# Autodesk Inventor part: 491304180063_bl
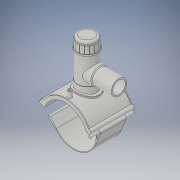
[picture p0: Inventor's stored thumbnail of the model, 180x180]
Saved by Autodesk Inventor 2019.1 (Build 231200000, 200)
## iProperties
Created: 2017-07
Part Number: 491304180063_bl
Material: Generic
Description: PLASSON TAPPING TEE SADDLE 180mm x 63mm
Document SubType Name: Modeling
Designer: KIM
Mass: 1712.7 g
Surface Area: 2671.49 cm^2
Volume: 1712.7 cm^3
Density: 1 g/cm^3
Appearance: Default
Author: KIM
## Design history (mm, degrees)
derived "491304.ipt"
feature "Solid1::491304.ipt" dims "ScaleForDerivedMember" = 10
feature "Solid2::491304.ipt" dims "ScaleForDerivedMember" = 10
feature "Solid4::491304.ipt" dims "ScaleForDerivedMember" = 10
feature "Solid5::491304.ipt" dims "ScaleForDerivedMember" = 10
tag "TaggingFeature1"
body "Solid1"
body "Solid2"
other parameters: "d1" = 101.118 [user parameter], "d2" = 281.6 [user parameter], "d3" = 45 [user parameter], "d4" = 176 [user parameter], "d5" = 0 [user parameter], "d6" = 0.1 [user parameter], "d8" = 0 [user parameter], "d40" = 108 [user parameter], "d41" = 97.65 [user parameter], "d43" = 0 [user parameter], "d45" = 0 [user parameter], "d47" = 156.159 [user parameter], "d78" = 125 [user parameter], "d79" = 15 [user parameter], "d80" = 70.4 [user parameter], "d82" = 5 deg [user parameter], "d84" = 4 [user parameter], "d85" = 14 [user parameter], "d86" = 0 [user parameter], "d87" = 3 [user parameter], "d88" = 0 [user parameter], "d97" = 3.52 [user parameter], "d98" = 0 [user parameter], "d102" = 1.8 [user parameter], "d120" = 140 deg [user parameter], "d123" = 606.708 [user parameter], "d126" = 0 [user parameter], "d153" = 176 [user parameter], "d154" = 0 [user parameter], "d159" = -15.7764 [user parameter], "d162" = 105.6 [user parameter], "d163" = 0 [user parameter], "d169" = 4.0905 [user parameter], "d172" = 0 [user parameter], "d173" = 1 [user parameter], "d176" = 20 deg [user parameter], "d177" = 12.6 [user parameter], "d180" = 0 [user parameter], "d184" = 10.08 [user parameter], "d187" = 99 [user parameter], "d188" = 15 [user parameter], "d189" = 12.6 [user parameter], "d190" = 0 [user parameter], "d191" = 135 [user parameter], "d195" = 90 deg [user parameter], "d197" = 0 [user parameter], "d199" = 0 [user parameter], "d200" = 12.6 [user parameter], "d202" = 0 [user parameter], "d203" = 195 [user parameter], "d206" = 75.6 [user parameter], "d207" = 146.25 [user parameter], "d208" = 152.1 [user parameter], "d209" = 181.35 [user parameter], "d210" = 76.86 [user parameter], "d212" = 72.45 [user parameter], "d213" = 39.15 [user parameter], "d216" = 0 [user parameter], "d217" = 18 [user parameter], "d218" = 9 [user parameter], "d219" = 1.8 [user parameter], "d224" = 0 [user parameter], "d259" = 50.4 [user parameter], "d260" = 63 [user parameter], "d263" = 176 [user parameter], "d265" = 0 [user parameter], "d267" = 13.00006 [user parameter], "d268" = 2.60001 [user parameter], "d269" = 2.60001 [user parameter], "d271" = 2.60001 [user parameter], "d273" = 0 [user parameter], "d274" = 23.56194 [user parameter], "d275" = 144 [user parameter], "d277" = 72 [user parameter], "d278" = 288 [user parameter], "d280" = 0 [user parameter], "d283" = 0 [user parameter], "d285" = 0 [user parameter], "d290" = 18 [user parameter], "d293" = 99 [user parameter], "d294" = 92.7 [user parameter], "d296" = 27 [user parameter], "d299" = 75 [user parameter], "d300" = 3 [user parameter], "d301" = 5 [user parameter], "d303" = 81.9 [user parameter], "d304" = 69.3 [user parameter], "d305" = 45 deg [user parameter], "d306" = 50.4 [user parameter], "d307" = 112.5 [user parameter], "d308" = 108 [user parameter], "d310" = 1 [user parameter], "B" = 176 [user parameter], "L" = 176 [user parameter], "d_t" = 6 [user parameter], "H2" = 195 [user parameter], "H1" = 75 [user parameter], "d_1" = 63 [user parameter]
